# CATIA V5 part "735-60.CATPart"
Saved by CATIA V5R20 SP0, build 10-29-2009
Part number: 735-60
Bounding box of the stored display mesh (mm): x -47.5 to 47.5, y -47.5 to 47.5, z -60 to 56
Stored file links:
  C:\Users\Utente\Desktop\IO LAVORO\3D X SITO CF\X SITO\735\735-60.CATPart
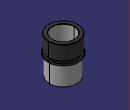
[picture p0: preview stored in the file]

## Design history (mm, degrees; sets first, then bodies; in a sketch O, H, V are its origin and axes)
Set1
  DatumSurface1 to DatumSurface25 "735-60"
Body1 (main body)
